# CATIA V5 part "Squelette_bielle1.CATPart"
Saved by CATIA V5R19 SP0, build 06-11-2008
Part number: Squelette_bielle1
Bounding box of the stored display mesh (mm): x -500 to 500, y 0 to 1443.75, z 0 to 134.485
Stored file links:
  C:\Users\Guillaume et Fanny\Documents\IFMA\2A\IAO\Squelette_bielle1.CATPart
  C:\Users\Guillaume et Fanny\Documents\IFMA\2A\IAO\Train d'aterrissage.CATProduct
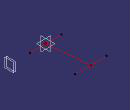
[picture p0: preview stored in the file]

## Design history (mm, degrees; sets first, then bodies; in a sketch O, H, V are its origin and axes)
Set1
  Point1: linked copy from another document
  Point2: linked copy from another document
Body1 (main body)
  Line1: type PtDir, Direction (1, 0, 0), Start -500, End 500, RefPoint Point1
  Line2: type PtDir, Direction (1, 0, 0), Start -500, End 500, RefPoint Point2
  Line3: type PtPt, SecondPoint Point2, FirstPoint Point1
  Plane1 "Plan.1170": type Offset, Offset 1170, RefPlane yz-plane
  Plane2 "Plan.1120": type Offset, Offset 1120, RefPlane yz-plane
